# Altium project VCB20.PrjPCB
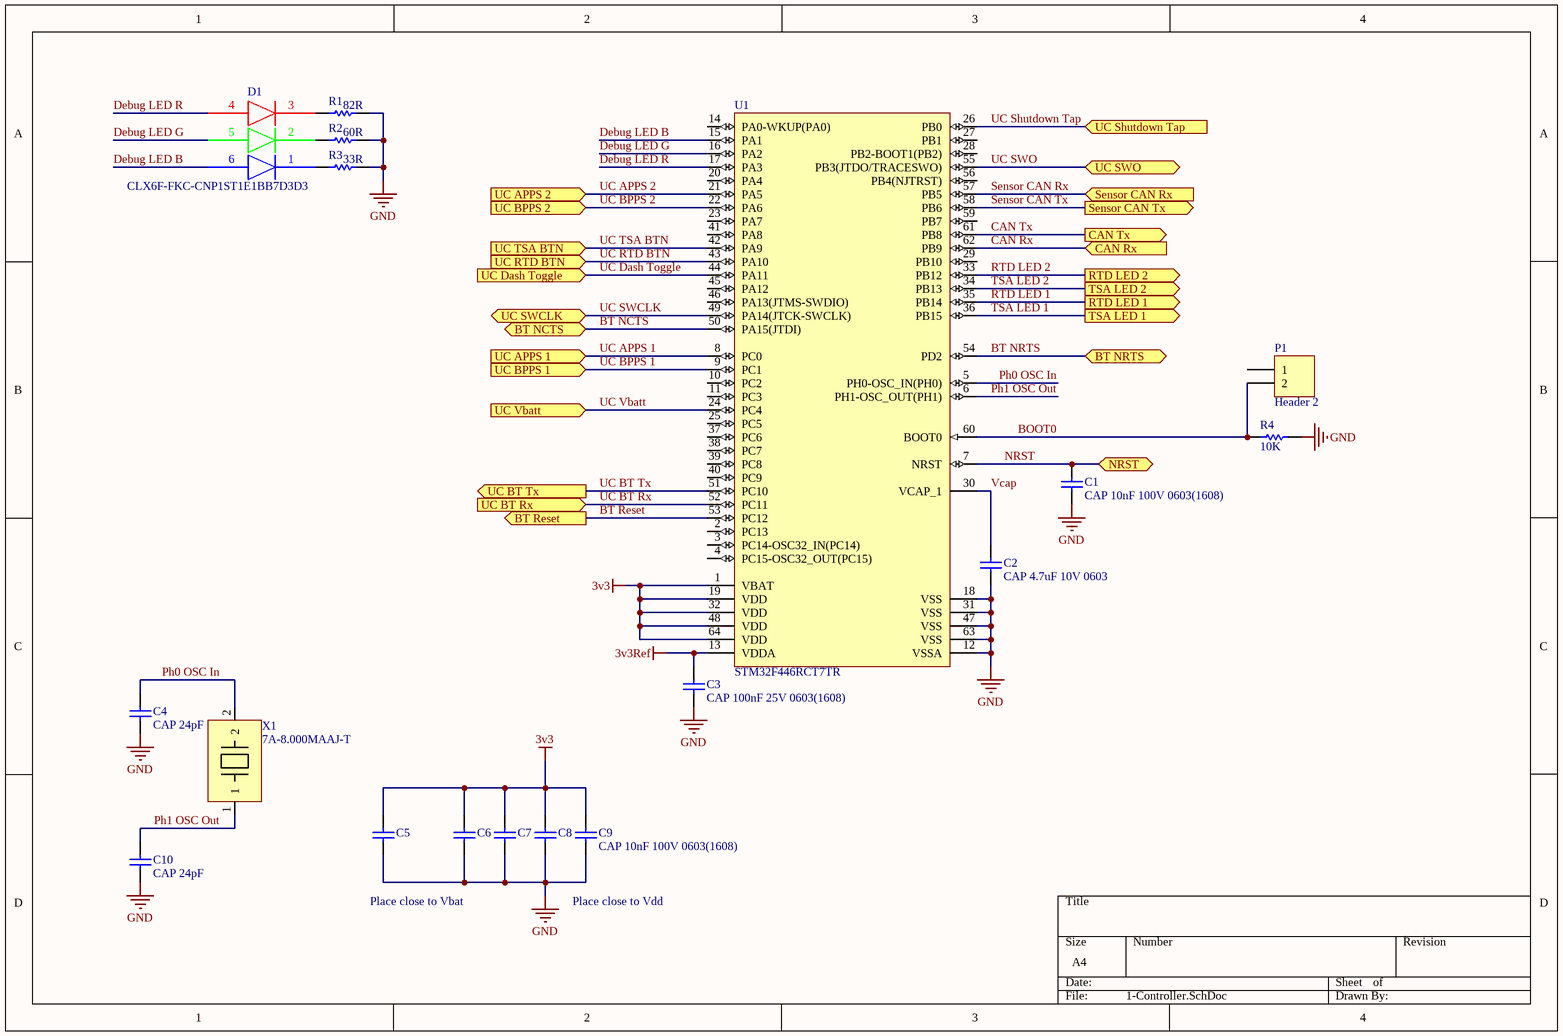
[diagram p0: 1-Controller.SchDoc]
8 sheets, 144 parts. Net scope: flat (ports and power ports of the same name join across sheets).
Board file: VCB2020.PcbDoc
Sheets:
  1-Controller.SchDoc
  2-Power.SchDoc
  3-CAN.SchDoc
  4-PPS.SchDoc
  5-Connector.SchDoc
  8-Bluetooth.SchDoc
  9-Other_Inputs.SchDoc
  10-DashLEDs.SchDoc

## Sheet 1-Controller.SchDoc
size A4

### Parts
C1  CAP 10nF 100V 0603(1608)  [CAPC0603(1608)100_M]
C2  CAP 4.7uF 10V 0603  [CAPC0603(1608)100_M]
C3  CAP 100nF 25V 0603(1608)  [CAPC0603(1608)100_N]
C4  CAP 24pF  [CAPC0603(1608)100_N]
C5  CAP 10nF 100V 0603(1608)  [CAPC0603(1608)100_M]  (value not drawn)
C6  CAP 10nF 100V 0603(1608)  [CAPC0603(1608)100_M]  (value not drawn)
C7  CAP 10nF 100V 0603(1608)  [CAPC0603(1608)100_M]  (value not drawn)
C8  CAP 10nF 100V 0603(1608)  [CAPC0603(1608)100_M]  (value not drawn)
C9  CAP 10nF 100V 0603(1608)  [CAPC0603(1608)100_M]
C10  CAP 24pF  [CAPC0603(1608)100_N]
D1  CLX6F-FKC-CNP1ST1E1BB7D3D3  [CLX6C-FKB]
P1  Header 2  [HDR1X2]
R1  82R  [RESC0603(1608)_N]
R2  60R  [RESC0603(1608)_N]
R3  33R  [RESC0603(1608)_N]
R4  10K  [RESC0603(1608)_N]
U1  STM32F446RCT7TR  [STM-LQFP64_L]
X1  7A-8.000MAAJ-T  [2-SMD, No Lead]

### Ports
BT NCTS (bidir), BT NRTS (bidir), BT Reset (out), CAN Rx (in), CAN Tx (out), NRST (bidir), RTD LED 1 (out), RTD LED 2 (out), Sensor CAN Rx (in), Sensor CAN Tx (out), TSA LED 1 (out), TSA LED 2 (out), UC APPS 1 (in), UC APPS 2 (in), UC BPPS 1 (in), UC BPPS 2 (in), UC BT Rx (in), UC BT Tx (out), UC Dash Toggle (in), UC RTD BTN (in), UC Shutdown Tap (in), UC SWCLK (bidir), UC SWO (bidir), UC TSA BTN (in), UC Vbatt (in)

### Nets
3v3: C5.2 C6.2 C7.2 C8.2 C9.2 U1.1(VBAT) U1.19(VDD) U1.32(VDD) U1.48(VDD) U1.64(VDD)
3v3Ref: C3.2 U1.13(VDDA)
GND: C1.1 C2.1 C3.1 C4.1 C5.1 C6.1 C7.1 C8.1 C9.1 C10.1 R1.2 R2.2 R3.2 R4.2 U1.12(VSSA) U1.18(VSS) U1.31(VSS) U1.47(VSS) U1.63(VSS)
BOOT0: P1.2 R4.1 U1.60(BOOT0)
BT NCTS: U1.50(PA15(JTDI)) ; port BT NCTS
BT NRTS: U1.54(PD2) ; port BT NRTS
BT Reset: U1.53(PC12) ; port BT Reset
CAN Rx: U1.62(PB9) ; port CAN Rx
CAN Tx: U1.61(PB8) ; port CAN Tx
Debug LED B: D1.6(B) U1.15(PA1)
Debug LED G: D1.5(G) U1.16(PA2)
Debug LED R: D1.4(R) U1.17(PA3)
NRST: C1.2 U1.7(NRST) ; port NRST
Ph0 OSC In: C4.2 U1.5(PH0-OSC_IN(PH0)) X1.2
Ph1 OSC Out: C10.2 U1.6(PH1-OSC_OUT(PH1)) X1.1
RTD LED 1: U1.35(PB14) ; port RTD LED 1
RTD LED 2: U1.33(PB12) ; port RTD LED 2
Sensor CAN Rx: U1.57(PB5) ; port Sensor CAN Rx
Sensor CAN Tx: U1.58(PB6) ; port Sensor CAN Tx
TSA LED 1: U1.36(PB15) ; port TSA LED 1
TSA LED 2: U1.34(PB13) ; port TSA LED 2
UC APPS 1: U1.8(PC0) ; port UC APPS 1
UC APPS 2: U1.21(PA5) ; port UC APPS 2
UC BPPS 1: U1.9(PC1) ; port UC BPPS 1
UC BPPS 2: U1.22(PA6) ; port UC BPPS 2
UC BT Rx: U1.52(PC11) ; port UC BT Rx
UC BT Tx: U1.51(PC10) ; port UC BT Tx
UC Dash Toggle: U1.44(PA11) ; port UC Dash Toggle
UC RTD BTN: U1.43(PA10) ; port UC RTD BTN
UC Shutdown Tap: U1.26(PB0) ; port UC Shutdown Tap
UC SWCLK: U1.49(PA14(JTCK-SWCLK)) ; port UC SWCLK
UC SWO: U1.55(PB3(JTDO/TRACESWO)) ; port UC SWO
UC TSA BTN: U1.42(PA9) ; port UC TSA BTN
UC Vbatt: U1.24(PC4) ; port UC Vbatt
Vcap: C2.2 U1.30(VCAP_1)
NetD1_1: D1.1(B) R3.1
NetD1_2: D1.2(G) R2.1
NetD1_3: D1.3(R) R1.1

Not connected (* = marked no-connect by the designer): P1 1; U1 2(PC13) 3(PC14-OSC32_IN(PC14)) 4(PC15-OSC32_OUT(PC15)) 10(PC2) 11(PC3) 14(PA0-WKUP(PA0)) 20(PA4) 23(PA7) 25(PC5) 27(PB1) 28(PB2-BOOT1(PB2)) 29(PB10) 37(PC6) 38(PC7) 39(PC8) 40(PC9) 41(PA8) 45(PA12) 46(PA13(JTMS-SWDIO)) 56(PB4(NJTRST)) 59(PB7)

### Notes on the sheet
- Place close to Vbat
- Place close to Vdd

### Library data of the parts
C1 C5-C9 = CMP-1035-02326-1: CAP 10nF 100V ±20% 0603 (1608 Metric) Thickness 1mm SMD; Case-EIA: 0603; Tolerance: Â±20%; Case-Metric: 1608
C2 = CMP-1035-02787-1: CAP 4.7uF 10V ±20% 0603 (1608 Metric) Thickness 1mm SMD; Case-EIA: 0603; Case-Metric: 1608; Tolerance: Â±20%
C3 = CMP-1035-02589-1: CAP 100nF 25V ±20% 0603 (1608 Metric) Thickness 1mm SMD; Case-EIA: 0603; Tolerance: Â±20%; Case-Metric: 1608
C4 C10 = CMP-1035-00843-1: CAP 24pF 16V ±2% 0603 (1608 Metric) Thickness 1mm SMD; Tolerance: Â±2%; Case-Metric: 1608; Case-EIA: 0603
D1 = LED - CLX6F-FKC-CNP1ST1E1BB7D3D3: Red, Green, Blue (RGB) 622nm Red, 530nm Green, 470nm Blue LED Indication - Discrete 2.1V Red, 2.7V Green, 3V Blue 6-SMD, J-Lead
P1 = Header 2: Header, 2-Pin
R1 = CMP-1012-00048-1: 82R 0.1W 5% 0603 (1608 Metric)  SMD; Case-Metric: 1608; Value: 82.00 Ohm; Case-EIA: 0603
R2 = CMP-1012-00372-1: 60R4 0.1W 1% 0603 (1608 Metric)  SMD; Case-EIA: 0603; Value: 60.40 Ohm; Case-Metric: 1608
R3 = CMP-1012-00038-1: 33R 0.1W 5% 0603 (1608 Metric)  SMD; Value: 33.00 Ohm; Case-EIA: 0603; Case-Metric: 1608
R4 = CMP-1012-00098-1: 10K 0.1W 5% 0603 (1608 Metric)  SMD; Case-EIA: 0603; Value: 10000.00 Ohm; Case-Metric: 1608
U1 = CMP-0243-00217-1: ARM Cortex-M4 32-bit MCU+FPU, 256 KB Flash, 128 KB Internal RAM, 50 I/Os, 64-Pin LQFP, -40 to 105 degC, Tape and Reel; Supply Voltage(Vcc) min (V): 1.7; D/A Converter: 2; Internal RAM Size (kB): 128; FLASH Size (Prog) (kB): 256; I/Os (High Current): 50; Operating Frequency(F) (Processor speed) (MHz): 180
X1 = 8MHz crystal, 7A-8.000MAAJ-T: Manufacturer: TXC CORPORATION; Frequency: 8MHz; Frequency Stability: ±30ppm; Load Capacitance: 18pF; ESR (Equivalent Series Resistance): 80 Ohm; Operating Mode: Fundamental

## Sheet 2-Power.SchDoc
size A4
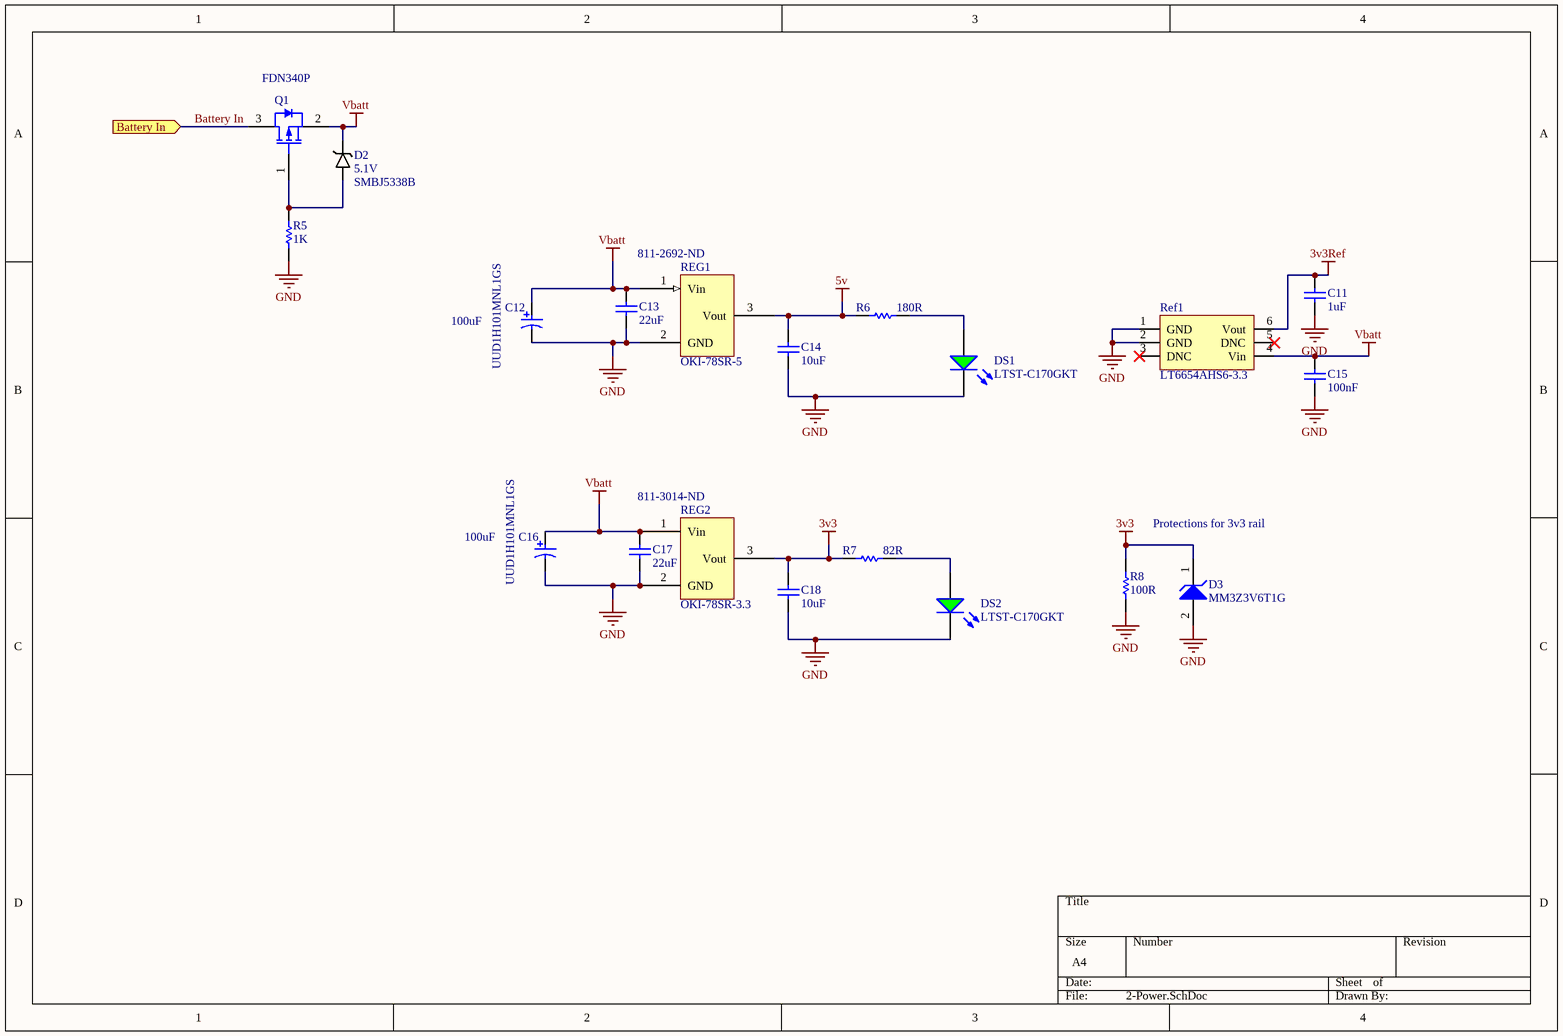
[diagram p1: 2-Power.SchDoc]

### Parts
C11  value 1uF  [1608[0603]]  (hidden comment: Cap)
C12  UUD1H101MNL1GS  [NIC-CAPA2-8X10_V]
C13  value 22uF  [C1210_M]  (hidden comment: Cap)
C14  value 10uF  [C1210_M]  (hidden comment: Cap)
C15  value 100nF  [1608[0603]]  (hidden comment: Cap)
C16  UUD1H101MNL1GS  [NIC-CAPA2-8X10_V]
C17  value 22uF  [C1210_M]  (hidden comment: Cap)
C18  value 10uF  [C1210_M]  (hidden comment: Cap)
D2  Reverse Voltage: 5.1V  Part Number: SMBJ5338B  [DO-214AA (SMB)]  (hidden comment: Zener Diode, 5.1V, 5W SMBJ5338B)
D3  MM3Z3V6T1G  [ONSC-SOD-323-2-477-02_V]
DS1  LTST-C170GKT  [LTST-C170GKT_V]
DS2  LTST-C170GKT  [LTST-C170GKT_V]
Q1  FDN340P  [FAIR-SSOT3L-3_V]
R5  value 1K  [1608[0603]]  (hidden comment: Res1)
R6  value 180R  [1608[0603]]  (hidden comment: Res1)
R7  value 82R  [1608[0603]]  (hidden comment: Res1)
R8  100R  [RESC1206(3216)_M]
Ref1  LT6654AHS6-3.3  [TSOT-23 S6]
REG1  OKI-78SR-5  Supplier Part Number 2: 811-2692-ND  [Reg - TH, 3 pin, 100 mil Pitch, HTL]
REG2  OKI-78SR-3.3  Supplier Part Number 2: 811-3014-ND  [Reg - TH, 3 pin, 100 mil Pitch, VTL]

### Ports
Battery In (in)

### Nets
3v3: C18.2 D3.1(K) R7.1 R8.2 REG2.3(Vout)
3v3Ref: C11.2 Ref1.6(Vout)
5v: C14.2 R6.1 REG1.3(Vout)
GND: C11.1 C12.2 C13.1 C14.1 C15.1 C16.2 C17.1 C18.1 D3.2(A) DS1.2(K) DS2.2(K) R5.1 R8.1 Ref1.1(GND) Ref1.2(GND) REG1.2(GND) REG2.2(GND)
Vbatt: C12.1 C13.2 C15.2 C16.1 C17.2 D2.K Q1.2(SOURCE) Ref1.4(Vin) REG1.1(Vin) REG2.1(Vin)
Battery In: Q1.3(DRAIN) ; port Battery In
NetD2_A: D2.A Q1.1(GATE) R5.2
NetDS1_1: DS1.1(A) R6.2
NetDS2_1: DS2.1(A) R7.2

Not connected (* = marked no-connect by the designer): Ref1 3(DNC)* 5(DNC)*

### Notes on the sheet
- (near C12) 100uF
- (near C16) 100uF
- Protections for 3v3 rail

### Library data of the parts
C11 = Cap: Capacitor; Manufacturer: Murata Electronics North America; Manufacturer Part Number: GRM188R61E105KA12D; Capacitance: 1µF; Tolerance: ±10%; Voltage - Rated: 25V; Temperature Coefficient: X5R
C12 C16 = CMP-0687-00073-1: Aluminum Electrolytic Capacitor, UD Series, Low Impedance, 100 uF, 50 V, + / - 20%, -55 to 105 degC, Chip Type, 8 x 10 mm D x L, Pb-Free, Reel; Manufacturer: Nichicon; Rated Ripple Current (at 100kHz): 300 mA; Tolerance Rated Capacitance: -20 to 20%; Packing: Dia382mm Reel; Impedance: 0.34 Ohm; Rated Voltage: 50 V; Endurance Time: 5000 h; Rated Capacitance: 100 uF; Capacitance: 100µF; Voltage Rating: 50V; Lifetime @ Temp.: 5000 Hrs @ 105°C; Polarization: Polar; Ripple Current: 300mA; Surface Mount Land Size: 0.327" L x 0.327" W (8.30mm x 8.30mm)
C13 C17 = Cap: Capacitor; Manufacturer: Yageo; Manufacturer Part Number: CC1210MKX5R8BB226; Capacitance: 22µF; Tolerance: ±20%; Voltage - Rated: 25V; Temperature Coefficient: X5R
C14 C18 = Cap: Capacitor; Manufacturer: Yageo; Manufacturer Part Number: CC1210ZKY5V8BB106; Capacitance: 10µF; Tolerance: -20%, +80%; Voltage - Rated: 25V; Temperature Coefficient: Y5V (F)
C15 = Cap: Capacitor; Manufacturer: Yageo; Manufacturer Part Number: CC0603KRX7R9BB104; Capacitance: 0.10µF; Tolerance: ±10%; Voltage - Rated: 50V; Temperature Coefficient: X7R
D3 = CMP-1060-00650-1: Zener Voltage Regulator, 300 mW, 2-Pin SOD-323, Pb-Free, Tape and Reel; Manufacturer: On Semiconductor; VZ Typ (V): 3.6; P Max (W): 0.3
DS1 DS2 = CMP-1674-00002-5: LED Uni-Color Green, 100 mW, 120 mA, -55 to 85 degC, 2-Pin SMD, RoHS, Tape and Reel; Manufacturer: Lite-On; Lens Color: Colorless; Lens Transparency: Clear; Millicandela Rating: 6mcd; Lens Style/Size: Rectangle with Flat Top, 1.40mm x 1.25mm; Voltage - Forward (Vf) (Typ): 2.1V; Current - Test: 10mA; Viewing Angle: 130°; Wavelength - Dominant: 569nm; Wavelength - Peak: 565nm
Q1 = CMP-2100-03638-1: Single P-Channel, Logic Level, PowerTrench(R) MOSFET, 2 A, 20 V, -55 to 150 degC, 3-Pin SOT-23, RoHS, Tape and Reel; Manufacturer: Fairchild Semiconductor; Fall Time: 11ns; Current Rating: -2A; Turn-On Delay Time: 10ns; Drain to Source Breakdown Voltage: -20V; Drain to Source Resistance: 60mOhm; Gate to Source Voltage (Vgs): 8V; Threshold Voltage: -800mV; Rds On Max: 70mOhm; Package Version: Rev. 3, 05/2015; Turn-Off Delay Time: 27ns; Power Dissipation: 500mW; Number of Elements: 1; Drain to Source Voltage (Vdss): 20V; Rise Time: 9ns; Input Capacitance: 779pF; Continuous Drain Current (ID): 2A
R5 = Res1: Resistor; Manufacturer: Panasonic Electronic Components; Manufacturer Part Number: ERJ-PA3F1001V; Tolerance: ±1%; Power (Watts): 0.25W, 1/4W; Temperature Coefficient: ±100ppm/°C
R6 = Res1: Resistor; Manufacturer: Yageo; Manufacturer Part Number: RC0603JR-07180RL; Resistance (Ohms): 180; Tolerance: ±5%; Power (Watts): 0.1W, 1/10W; Temperature Coefficient: ±100ppm/°C
R7 = Res1: Resistor; Manufacturer: Yageo; Manufacturer Part Number: RC0603JR-0782RL; Resistance (Ohms): 82; Tolerance: ±5%; Power (Watts): 0.1W, 1/10W; Temperature Coefficient: ±100ppm/°C
R8 = CMP-1014-00050-1: 100R 0.25W 5% 1206 (3216 Metric)  SMD; Case-EIA: 1206; Value: 100.00 Ohm; Case-Metric: 3216
Ref1 = LT6654AHS6-3.3: Manufacturer: Linear Technology; Reference Type: Series; Output Type: Fixed; Voltage - Output (Min/Fixed): 3.3V; Current - Output: 10mA; Tolerance: ±0.05%; Temperature Coefficient: 10ppm/°C; Noise - 0.1Hz to 10Hz: 1.7ppmp-p; Noise - 10Hz to 10kHz: 2ppmrms; Voltage - Input: 3.8 V ~ 36 V; Current - Supply: 600µA
REG1 = OKI-78SR-5: Manufacturer: Murata Power Solutions Inc.; Manufacturer Part Number: OKI-78SR-3.3/1.5-W36-C; Power (Watts) - Manufacture Series: 5W; Number of Outputs: 1; Voltage - Input (Min): 7V; Voltage - Input (Max): 36V; Voltage - Output 1: 3.3V; Current - Output (Max): 1.5A; Efficiency: 85.5%
REG2 = OKI-78SR-5: 3.3V DCDC; Manufacturer: Murata Power Solutions Inc.; Manufacturer Part Number: OKI-78SR-3.3/1.5-W36H-C; Power (Watts) - Manufacture Series: 5W; Number of Outputs: 1; Voltage - Input (Min): 7V; Voltage - Input (Max): 36V; Current - Output (Max): 1.5A; Efficiency: 85.5%

## Sheet 3-CAN.SchDoc
size A4
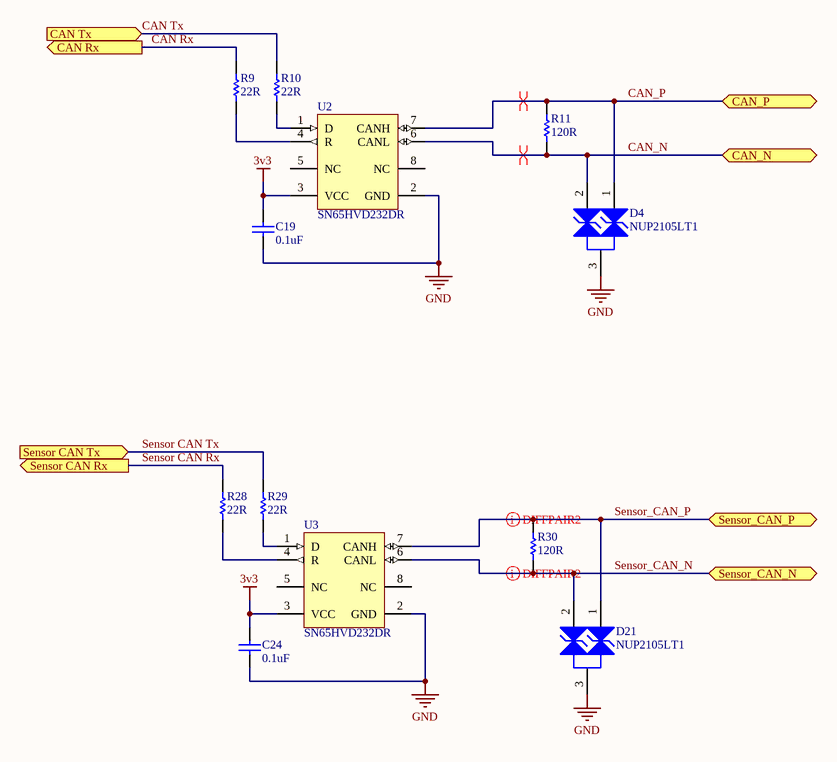
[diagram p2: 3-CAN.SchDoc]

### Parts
C19  0.1uF  [CAPC1608X90X30NL10T20]
C24  0.1uF  [CAPC1608X90X30NL10T20]
D4  NUP2105LT1  [ONSC-SOT-23-3-318-08_V]
D21  NUP2105LT1  [ONSC-SOT-23-3-318-08_V]
R9  22R  [RESC0603(1608)_N]
R10  22R  [RESC0603(1608)_N]
R11  120R  [RESC0603(1608)_N]
R28  22R  [RESC0603(1608)_N]
R29  22R  [RESC0603(1608)_N]
R30  120R  [RESC0603(1608)_N]
U2  SN65HVD232DR  [D0008A_M]
U3  SN65HVD232DR  [D0008A_M]

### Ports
CAN Rx (out), CAN Tx (in), CAN_N (bidir), CAN_P (bidir), Sensor CAN Rx (out), Sensor CAN Tx (in), Sensor_CAN_N (bidir), Sensor_CAN_P (bidir)

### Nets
3v3: C19.2 C24.2 U2.3(VCC) U3.3(VCC)
GND: C19.1 C24.1 D4.3(K) D21.3(K) U2.2(GND) U3.2(GND)
CAN Rx: R9.2 ; port CAN Rx
CAN Tx: R10.2 ; port CAN Tx
CAN_N: D4.2(K) R11.1 U2.6(CANL) ; port CAN_N
CAN_P: D4.1(K) R11.2 U2.7(CANH) ; port CAN_P
Sensor CAN Rx: R28.2 ; port Sensor CAN Rx
Sensor CAN Tx: R29.2 ; port Sensor CAN Tx
Sensor_CAN_N: D21.2(K) R30.1 U3.6(CANL) ; port Sensor_CAN_N
Sensor_CAN_P: D21.1(K) R30.2 U3.7(CANH) ; port Sensor_CAN_P
NetR9_1: R9.1 U2.4(R)
NetR10_1: R10.1 U2.1(D)
NetR28_1: R28.1 U3.4(R)
NetR29_1: R29.1 U3.1(D)

Not connected (* = marked no-connect by the designer): U2 5(NC) 8(NC); U3 5(NC) 8(NC)

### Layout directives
differential pair: CAN_N, CAN_P, Sensor_CAN_N, Sensor_CAN_P

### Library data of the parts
C19 C24 = CMP-2000-06092-1: Chip Capacitor, 100 nF, +/- 10%, 50 V, -55 to 125 degC, 0603 (1608 Metric), RoHS, Tape and Reel; Manufacturer: SamsungElectro-Mechanics; Product Length: 1.6mm; Voltage: 50Vdc; Product Height: 0.8mm; Rad Hard: No; Dielectric: X7R
D4 D21 = CMP-1063-00165-1: Dual Line CAN Bus Protector, 3-Pin SOT-23, Tape and Reel; Manufacturer: On Semiconductor; PPK Max (W): 350; IR Max (uA): 0.1; Number of Lines: 2; V(BR) Min (V): 26.2; Direction: Bidirectional; C Max (pF): 30
R9 R10 R28 R29 = CMP-1012-00034-1: 22R 0.1W 5% 0603 (1608 Metric)  SMD; Value: 22.00 Ohm; Case-EIA: 0603; Case-Metric: 1608
R11 R30 = CMP-1012-00052-1: 120R 0.1W 5% 0603 (1608 Metric)  SMD; Case-EIA: 0603; Value: 120.00 Ohm; Case-Metric: 1608
U2 U3 = CMP-0315-00075-2: 3.3 V Can Transceiver, 17 mA, -40 to 85 degC, 8-pin SOIC (D), Green (RoHS & no Sb/Br); Manufacturer: Texas Instruments; Supply Voltage(s)(V): 3.3; Receivers Per Package: 1; ICC(Max)(mA): 17; Rating: Catalog; Transient Pulse Protection(V): -25 to 25

## Sheet 4-PPS.SchDoc
size A4
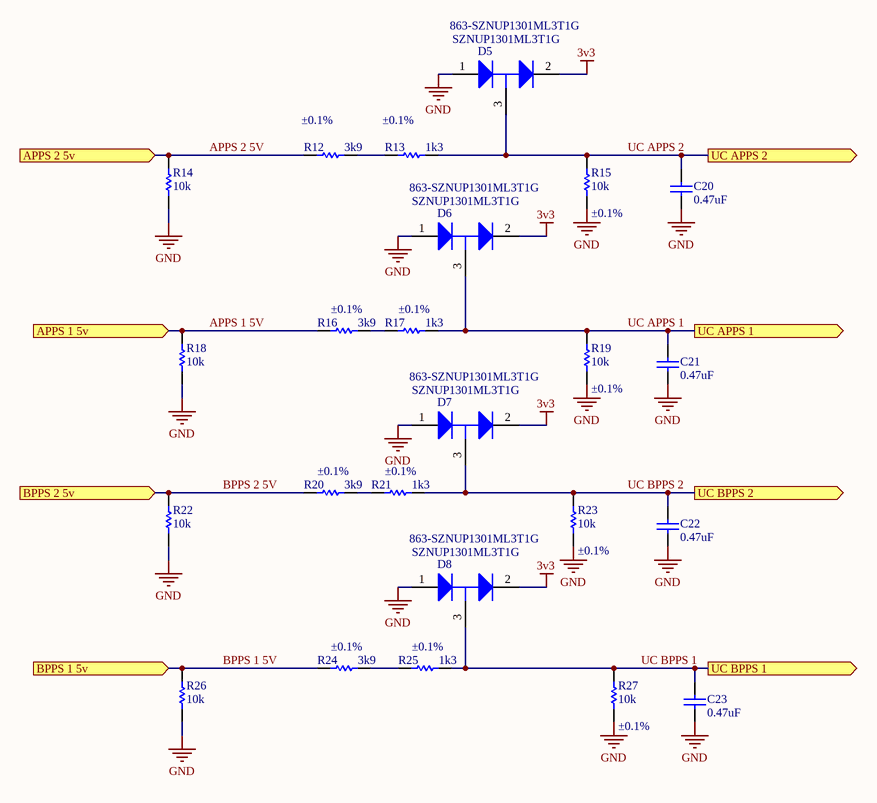
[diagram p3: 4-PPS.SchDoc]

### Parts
C20  value 0.47uF  [1608[0603]]  (hidden comment: Cap)
C21  value 0.47uF  [1608[0603]]  (hidden comment: Cap)
C22  value 0.47uF  [1608[0603]]  (hidden comment: Cap)
C23  value 0.47uF  [1608[0603]]  (hidden comment: Cap)
D5  SZNUP1301ML3T1G  Supplier Part Number 1: 863-SZNUP1301ML3T1G  [ONSC-SOT-23-3-318-08_V]
D6  SZNUP1301ML3T1G  Supplier Part Number 1: 863-SZNUP1301ML3T1G  [ONSC-SOT-23-3-318-08_V]
D7  SZNUP1301ML3T1G  Supplier Part Number 1: 863-SZNUP1301ML3T1G  [ONSC-SOT-23-3-318-08_V]
D8  SZNUP1301ML3T1G  Supplier Part Number 1: 863-SZNUP1301ML3T1G  [ONSC-SOT-23-3-318-08_V]
R12  value 3k9  Tolerance: ±0.1%  [1608[0603]]  (hidden comment: Res1)
R13  value 1k3  Tolerance: ±0.1%  [1608[0603]]  (hidden comment: Res1)
R14  value 10k  [1608[0603]]  (hidden comment: Res1)
R15  value 10k  Tolerance: ±0.1%  [1608[0603]]  (hidden comment: Res1)
R16  value 3k9  Tolerance: ±0.1%  [1608[0603]]  (hidden comment: Res1)
R17  value 1k3  Tolerance: ±0.1%  [1608[0603]]  (hidden comment: Res1)
R18  value 10k  [1608[0603]]  (hidden comment: Res1)
R19  value 10k  Tolerance: ±0.1%  [1608[0603]]  (hidden comment: Res1)
R20  value 3k9  Tolerance: ±0.1%  [1608[0603]]  (hidden comment: Res1)
R21  value 1k3  Tolerance: ±0.1%  [1608[0603]]  (hidden comment: Res1)
R22  value 10k  [1608[0603]]  (hidden comment: Res1)
R23  value 10k  Tolerance: ±0.1%  [1608[0603]]  (hidden comment: Res1)
R24  value 3k9  Tolerance: ±0.1%  [1608[0603]]  (hidden comment: Res1)
R25  value 1k3  Tolerance: ±0.1%  [1608[0603]]  (hidden comment: Res1)
R26  value 10k  [1608[0603]]  (hidden comment: Res1)
R27  value 10k  Tolerance: ±0.1%  [1608[0603]]  (hidden comment: Res1)

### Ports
APPS 1 5v (in), APPS 2 5v (in), BPPS 1 5v (in), BPPS 2 5v (in), UC APPS 1 (out), UC APPS 2 (out), UC BPPS 1 (out), UC BPPS 2 (out)

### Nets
3v3: D5.2(K) D6.2(K) D7.2(K) D8.2(K)
GND: C20.1 C21.1 C22.1 C23.1 D5.1(A) D6.1(A) D7.1(A) D8.1(A) R14.1 R15.1 R18.1 R19.1 R22.1 R23.1 R26.1 R27.1
APPS 1 5V: R16.1 R18.2 ; port APPS 1 5v
APPS 2 5V: R12.1 R14.2 ; port APPS 2 5v
BPPS 1 5V: R24.1 R26.2 ; port BPPS 1 5v
BPPS 2 5V: R20.1 R22.2 ; port BPPS 2 5v
UC APPS 1: C21.2 D6.3(K/A) R17.2 R19.2 ; port UC APPS 1
UC APPS 2: C20.2 D5.3(K/A) R13.2 R15.2 ; port UC APPS 2
UC BPPS 1: C23.2 D8.3(K/A) R25.2 R27.2 ; port UC BPPS 1
UC BPPS 2: C22.2 D7.3(K/A) R21.2 R23.2 ; port UC BPPS 2
NetR12_2: R12.2 R13.1
NetR16_2: R16.2 R17.1
NetR20_2: R20.2 R21.1
NetR24_2: R24.2 R25.1

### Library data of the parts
C20-C23 = Cap: Capacitor; Manufacturer: Yageo; Manufacturer Part Number: CC0603KRX7R8BB474; Capacitance: 0.47µF; Tolerance: ±10%; Voltage - Rated: 25V; Temperature Coefficient: X7R
D5-D8 = CMP-1063-00171-1: Low Capacitance Diode Array for ESD Protection in a Single Data Line, 3-Pin SOT-23, Pb-Free, Tape and Reel; Manufacturer: On Semiconductor; C Max (pF): 0.9; Direction: Bidirectional; V(BR) Min (V): 70; Number of Lines: 1
R12 R16 R20 R24 = Res1: Resistor; Manufacturer: Yageo; Manufacturer Part Number: RT0603BRD073K9L; Resistance (Ohms): 3.9k; Power (Watts): 0.1W, 1/10W; Temperature Coefficient: ±25ppm/°C
R13 R17 R21 R25 = Res1: Resistor; Manufacturer: Yageo; Manufacturer Part Number: RT0603BRD071K3L; Resistance (Ohms): 1.3k; Power (Watts): 0.1W, 1/10W; Temperature Coefficient: ±25ppm/°C
R14 R18 R22 R26 = Res1: Resistor; Manufacturer: Yageo; Manufacturer Part Number: RC0603JR-0710KL; Tolerance: ±5%; Power (Watts): 0.1W, 1/10W; Temperature Coefficient: ±100ppm/°C
R15 R19 R23 R27 = Res1: Resistor; Manufacturer: Yageo; Manufacturer Part Number: RT0603BRD0710KL; Power (Watts): 0.1W, 1/10W; Temperature Coefficient: ±25ppm/°C

## Sheet 5-Connector.SchDoc
size A4
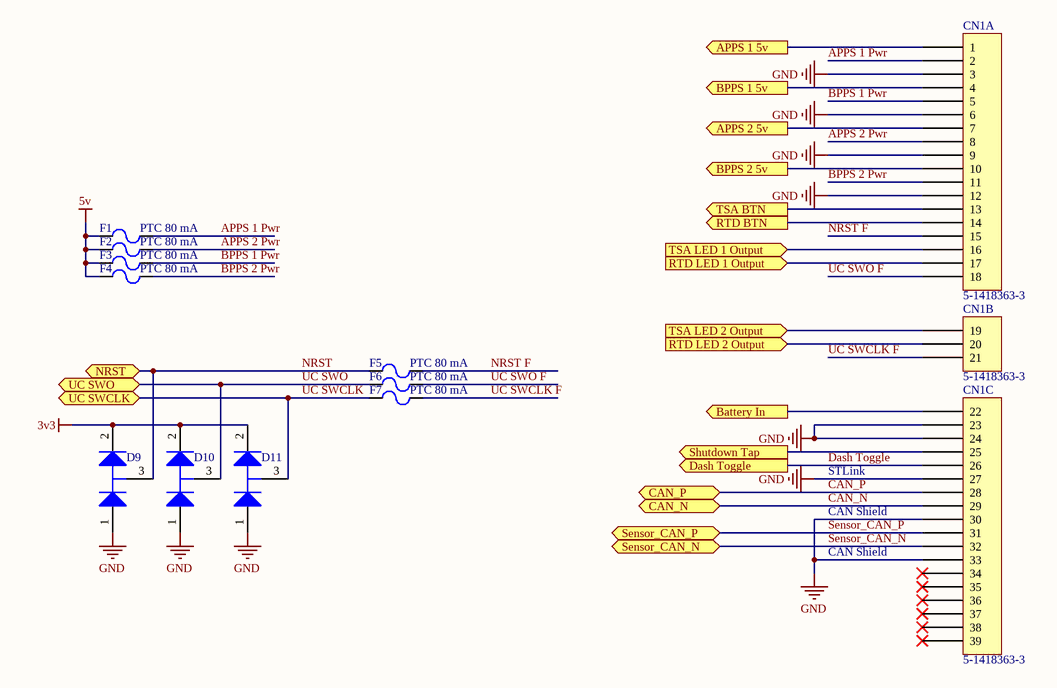
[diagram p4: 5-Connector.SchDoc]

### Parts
CN1  5-1418363-3  [5-1418363-3]  (parts A,B,C of 3)
D9  SZNUP1301ML3T1G  [ONSC-SOT-23-3-318-08_V]  (value not drawn)
D10  SZNUP1301ML3T1G  [ONSC-SOT-23-3-318-08_V]  (value not drawn)
D11  SZNUP1301ML3T1G  [ONSC-SOT-23-3-318-08_V]  (value not drawn)
F1  PTC 80 mA  [0603 fuse]
F2  PTC 80 mA  [0603 fuse]
F3  PTC 80 mA  [0603 fuse]
F4  PTC 80 mA  [0603 fuse]
F5  PTC 80 mA  [0603 fuse]
F6  PTC 80 mA  [0603 fuse]
F7  PTC 80 mA  [0603 fuse]

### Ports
APPS 1 5v (out), APPS 2 5v (out), Battery In (out), BPPS 1 5v (out), BPPS 2 5v (out), CAN_N (bidir), CAN_P (bidir), Dash Toggle (out), NRST (bidir), RTD BTN (out), RTD LED 1 Output (in), RTD LED 2 Output (in), Sensor_CAN_N (bidir), Sensor_CAN_P (bidir), Shutdown Tap (out), TSA BTN (out), TSA LED 1 Output (in), TSA LED 2 Output (in), UC SWCLK (bidir), UC SWO (bidir)

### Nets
3v3: D9.2(K) D10.2(K) D11.2(K)
5v: F1.1 F2.1 F3.1 F4.1
GND: CN1.3 CN1.6 CN1.9 CN1.12 CN1.23 CN1.24 CN1.27 CN1.30 CN1.33 D9.1(A) D10.1(A) D11.1(A)
APPS 1 5V: CN1.1 ; port APPS 1 5v
APPS 1 Pwr: CN1.2 F1.2
APPS 2 5V: CN1.7 ; port APPS 2 5v
APPS 2 Pwr: CN1.8 F2.2
Battery In: CN1.22 ; port Battery In
BPPS 1 5V: CN1.4 ; port BPPS 1 5v
BPPS 1 Pwr: CN1.5 F3.2
BPPS 2 5V: CN1.10 ; port BPPS 2 5v
BPPS 2 Pwr: CN1.11 F4.2
CAN_N: CN1.29 ; port CAN_N
CAN_P: CN1.28 ; port CAN_P
Dash Toggle: CN1.26 ; port Dash Toggle
NRST: D9.3(K/A) F5.1 ; port NRST
NRST F: CN1.15 F5.2
RTD BTN: CN1.14 ; port RTD BTN
RTD LED Output 1: CN1.17 ; port RTD LED 1 Output
RTD LED Output 2: CN1.20 ; port RTD LED 2 Output
Sensor_CAN_N: CN1.32 ; port Sensor_CAN_N
Sensor_CAN_P: CN1.31 ; port Sensor_CAN_P
Shutdown_Tap: CN1.25 ; port Shutdown Tap
TSA BTN: CN1.13 ; port TSA BTN
TSA LED Output 1: CN1.16 ; port TSA LED 1 Output
TSA LED Output 2: CN1.19 ; port TSA LED 2 Output
UC SWCLK: D11.3(K/A) F7.1 ; port UC SWCLK
UC SWCLK F: CN1.21 F7.2
UC SWO: D10.3(K/A) F6.1 ; port UC SWO
UC SWO F: CN1.18 F6.2

Not connected (* = marked no-connect by the designer): CN1 34* 35* 36* 37* 38* 39*

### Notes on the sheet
- STLink
- CAN Shield

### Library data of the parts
CN1 = 5-1418363-3: Levyseal 90 degree 39 pin header
D9-D11 = CMP-1063-00171-1: as D5 on sheet 4-PPS
F1-F7 = PTC fuse 80mA 0ZCM0008FF2G: 0ZCM0008FF2G

## Sheet 8-Bluetooth.SchDoc
size A4
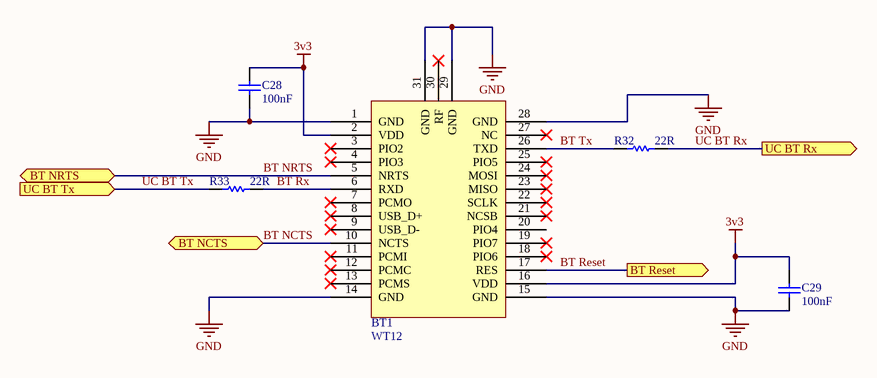
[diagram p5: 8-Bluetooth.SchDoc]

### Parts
BT1  WT12  [WT12]
C28  value 100nF  [1608[0603]]  (hidden comment: Cap)
C29  value 100nF  [1608[0603]]  (hidden comment: Cap)
R32  value 22R  [1608[0603]]  (hidden comment: Res1)
R33  value 22R  [1608[0603]]  (hidden comment: Res1)

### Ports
BT NCTS (bidir), BT NRTS (bidir), BT Reset (out), UC BT Rx (out), UC BT Tx (in)

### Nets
3v3: BT1.2(VDD) BT1.16(VDD) C28.2 C29.2
GND: BT1.1(GND) BT1.14(GND) BT1.15(GND) BT1.28(GND) BT1.29(GND) BT1.31(GND) C28.1 C29.1
BT NCTS: BT1.10(NCTS) ; port BT NCTS
BT NRTS: BT1.5(NRTS) ; port BT NRTS
BT Reset: BT1.17(RES) ; port BT Reset
BT Rx: BT1.6(RXD) R33.2
BT Tx: BT1.26(TXD) R32.1
UC BT Rx: R32.2 ; port UC BT Rx
UC BT Tx: R33.1 ; port UC BT Tx

Not connected (* = marked no-connect by the designer): BT1 3(PIO2)* 4(PIO3)* 7(PCMO)* 8(USB_D+)* 9(USB_D-)* 11(PCMI)* 12(PCMC)* 13(PCMS)* 18(PIO6)* 19(PIO7)* 20(PIO4) 21(NCSB)* 22(SCLK)* 23(MISO)* 24(MOSI)* 25(PIO5)* 27(NC)* 30(RF)*

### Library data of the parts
C28 C29 = Cap: as C15 on sheet 2-Power
R32 R33 = Res1: Resistor; Manufacturer: Yageo; Manufacturer Part Number: RC0603JR-0722RL; Resistance (Ohms): 22; Tolerance: ±5%; Power (Watts): 0.1W, 1/10W; Temperature Coefficient: ±100ppm/°C

## Sheet 9-Other_Inputs.SchDoc
size A4
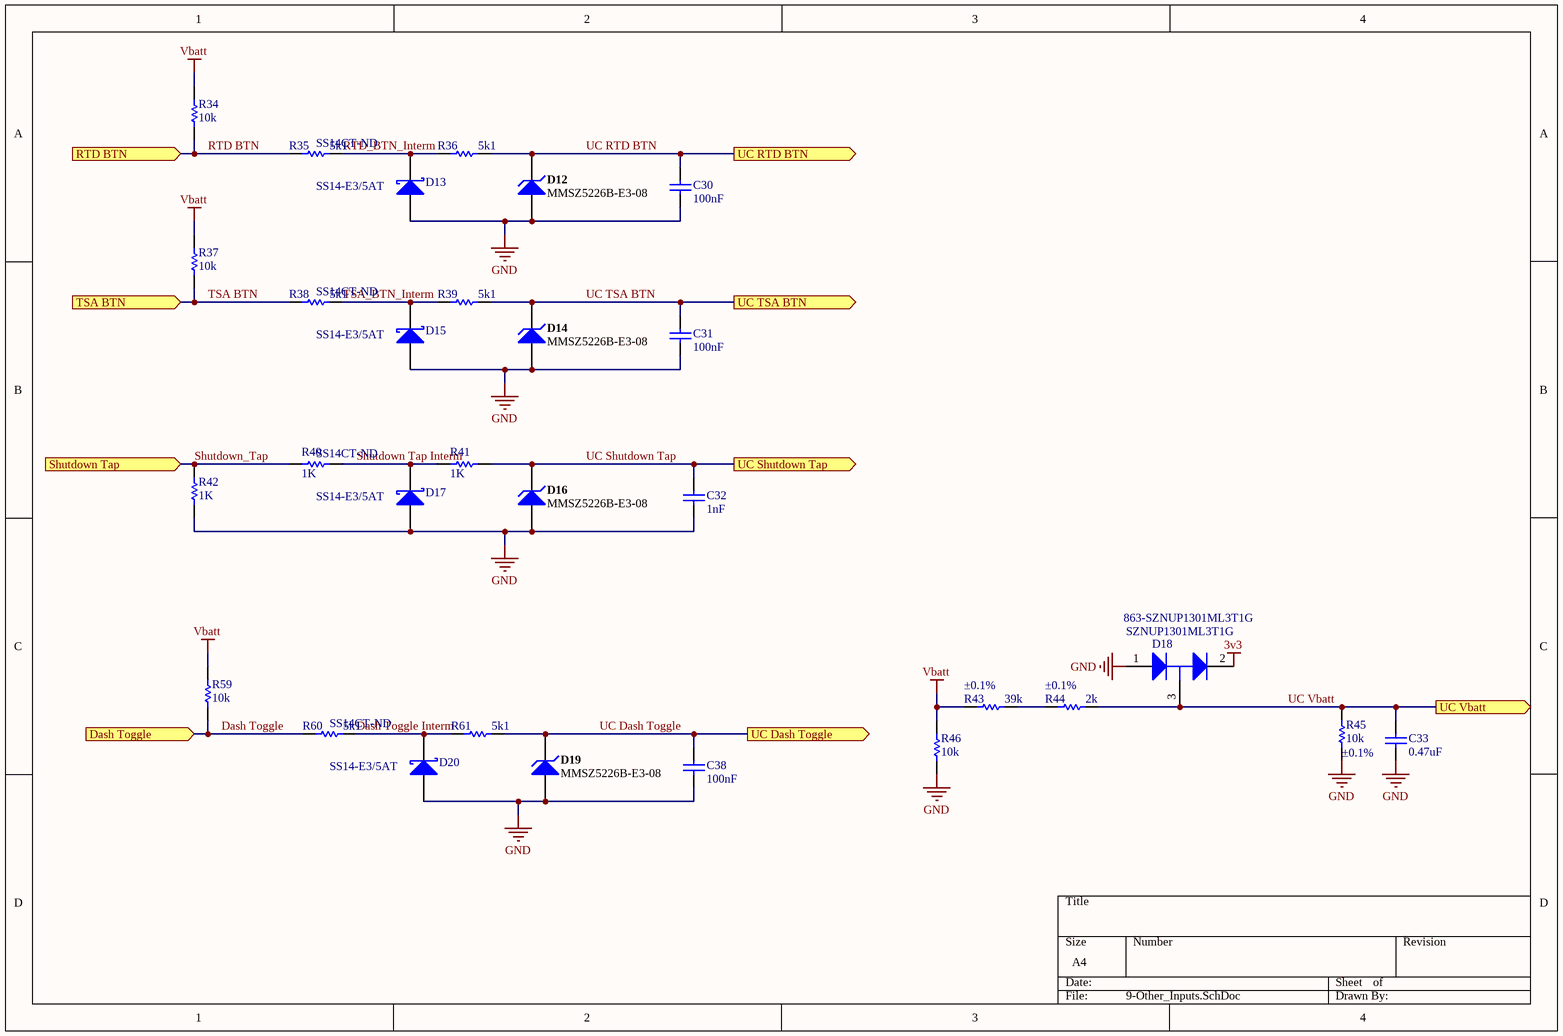
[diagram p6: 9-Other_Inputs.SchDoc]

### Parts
C30  value 100nF  [1608[0603]]  (hidden comment: Cap)
C31  value 100nF  [1608[0603]]  (hidden comment: Cap)
C32  value 1nF  [1608[0603]]  (hidden comment: Cap)
C33  value 0.47uF  [1608[0603]]  (hidden comment: Cap)
C38  value 100nF  [1608[0603]]  (hidden comment: Cap)
D12  MMSZ5226B-E3-08  [VISH-SOD-123-2_V]
D13  SS14-E3/5AT  Supplier Part Number 1: SS14CT-ND  [VISH-DO-214AC-2_V]
D14  MMSZ5226B-E3-08  [VISH-SOD-123-2_V]
D15  SS14-E3/5AT  Supplier Part Number 1: SS14CT-ND  [VISH-DO-214AC-2_V]
D16  MMSZ5226B-E3-08  [VISH-SOD-123-2_V]
D17  SS14-E3/5AT  Supplier Part Number 1: SS14CT-ND  [VISH-DO-214AC-2_V]
D18  SZNUP1301ML3T1G  Supplier Part Number 1: 863-SZNUP1301ML3T1G  [ONSC-SOT-23-3-318-08_V]
D19  MMSZ5226B-E3-08  [VISH-SOD-123-2_V]
D20  SS14-E3/5AT  Supplier Part Number 1: SS14CT-ND  [VISH-DO-214AC-2_V]
R34  value 10k  [1608[0603]]  (hidden comment: Res1)
R35  value 5k1  [1608[0603]]  (hidden comment: Res1)
R36  value 5k1  [1608[0603]]  (hidden comment: Res1)
R37  value 10k  [1608[0603]]  (hidden comment: Res1)
R38  value 5k1  [1608[0603]]  (hidden comment: Res1)
R39  value 5k1  [1608[0603]]  (hidden comment: Res1)
R40  value 1K  [1608[0603]]  (hidden comment: Res1)
R41  value 1K  [1608[0603]]  (hidden comment: Res1)
R42  value 1K  [1608[0603]]  (hidden comment: Res1)
R43  value 39k  Tolerance: ±0.1%  [1608[0603]]  (hidden comment: Res1)
R44  value 2k  Tolerance: ±0.1%  [1608[0603]]  (hidden comment: Res1)
R45  value 10k  Tolerance: ±0.1%  [1608[0603]]  (hidden comment: Res1)
R46  value 10k  [1608[0603]]  (hidden comment: Res1)
R59  value 10k  [1608[0603]]  (hidden comment: Res1)
R60  value 5k1  [1608[0603]]  (hidden comment: Res1)
R61  value 5k1  [1608[0603]]  (hidden comment: Res1)

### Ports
Dash Toggle (in), RTD BTN (in), Shutdown Tap (in), TSA BTN (in), UC Dash Toggle (out), UC RTD BTN (out), UC Shutdown Tap (out), UC TSA BTN (out), UC Vbatt (out)

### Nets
3v3: D18.2(K)
GND: C30.1 C31.1 C32.1 C33.1 C38.1 D12.1(A) D13.1(A) D14.1(A) D15.1(A) D16.1(A) D17.1(A) D18.1(A) D19.1(A) D20.1(A) R42.1 R45.1 R46.1
Vbatt: R34.2 R37.2 R43.1 R46.2 R59.2
Dash Toggle: R59.1 R60.1 ; port Dash Toggle
Dash Toggle Interm: D20.2(K) R60.2 R61.1
RTD BTN: R34.1 R35.1 ; port RTD BTN
RTD_BTN_Interm: D13.2(K) R35.2 R36.1
Shutdown Tap Interm: D17.2(K) R40.1 R41.2
Shutdown_Tap: R40.2 R42.2 ; port Shutdown Tap
TSA BTN: R37.1 R38.1 ; port TSA BTN
TSA_BTN_Interm: D15.2(K) R38.2 R39.1
UC Dash Toggle: C38.2 D19.2(K) R61.2 ; port UC Dash Toggle
UC RTD BTN: C30.2 D12.2(K) R36.2 ; port UC RTD BTN
UC Shutdown Tap: C32.2 D16.2(K) R41.1 ; port UC Shutdown Tap
UC TSA BTN: C31.2 D14.2(K) R39.2 ; port UC TSA BTN
UC Vbatt: C33.2 D18.3(K/A) R44.2 R45.2 ; port UC Vbatt
NetR43_2: R43.2 R44.1

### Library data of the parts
C30 C31 C38 = Cap: as C15 on sheet 2-Power
C32 = Cap: Capacitor; Manufacturer: Yageo; Manufacturer Part Number: CC0603KRX7R9BB102; Capacitance: 1000pF; Tolerance: ±10%; Voltage - Rated: 50V; Temperature Coefficient: X7R
C33 = Cap: as C20 on sheet 4-PPS
D12 D14 D16 D19 = CMP-0931-00026-1: Small Signal Zener Diode, 3.3 V +/- 5%, -55 to 155 degC, 2-Pin SOD-123, RoHS, Tape and Reel; Manufacturer: Vishay Semiconductor; Manufacturer Part Number: MMSZ5226B-7-F; Tolerance: +/- 5%; Test Current (IZT1) (mA): 20; Power Dissipation (mW): 500; Int. Construction: Single; Zener Impedance (IZT1) (Max.) (Ohm): 28; Zener Voltage (NOM.) (V): 3.3; Voltage - Zener (Nom) (Vz): 3.3V; Power - Max: 500mW; Impedance (Max) (Zzt): 28 Ohm; Current - Reverse Leakage @ Vr: 25µA @ 1V; Voltage - Forward (Vf) (Max) @ If: 900mV @ 10mA
D13 D15 D17 D20 = CMP-0549-00004-1: Schottky Barrier Rectifier, 40 V Maximum DC Blocking Voltage, -65 to 125 degC, 2-Pin SMA Case, RoHS; Manufacturer: Vishay Semiconductor; IFSM: 40 A; IF(AV): 1 A Max.; VRRM: 40 V Max.; VRMS: 28 V Max.
D18 = CMP-1063-00171-1: as D5 on sheet 4-PPS
R34 R37 R46 R59 = Res1: as R14 on sheet 4-PPS
R35 R36 R38 R39 R60 R61 = Res1: Resistor; Manufacturer: Yageo; Manufacturer Part Number: RC0603JR-075K1L; Resistance (Ohms): 5.1k; Tolerance: ±5%; Power (Watts): 0.1W, 1/10W; Temperature Coefficient: ±100ppm/°C
R40-R42 = Res1: as R5 on sheet 2-Power
R43 = Res1: Resistor; Manufacturer: Yageo; Manufacturer Part Number: RT0603BRD0739KL; Power (Watts): 0.1W, 1/10W; Temperature Coefficient: ±25ppm/°C
R44 = Res1: Resistor; Manufacturer: Yageo; Manufacturer Part Number: AT0603BRD072KL; Power (Watts): 0.1W, 1/10W; Temperature Coefficient: ±25ppm/°C
R45 = Res1: as R15 on sheet 4-PPS

## Sheet 10-DashLEDs.SchDoc
size A4
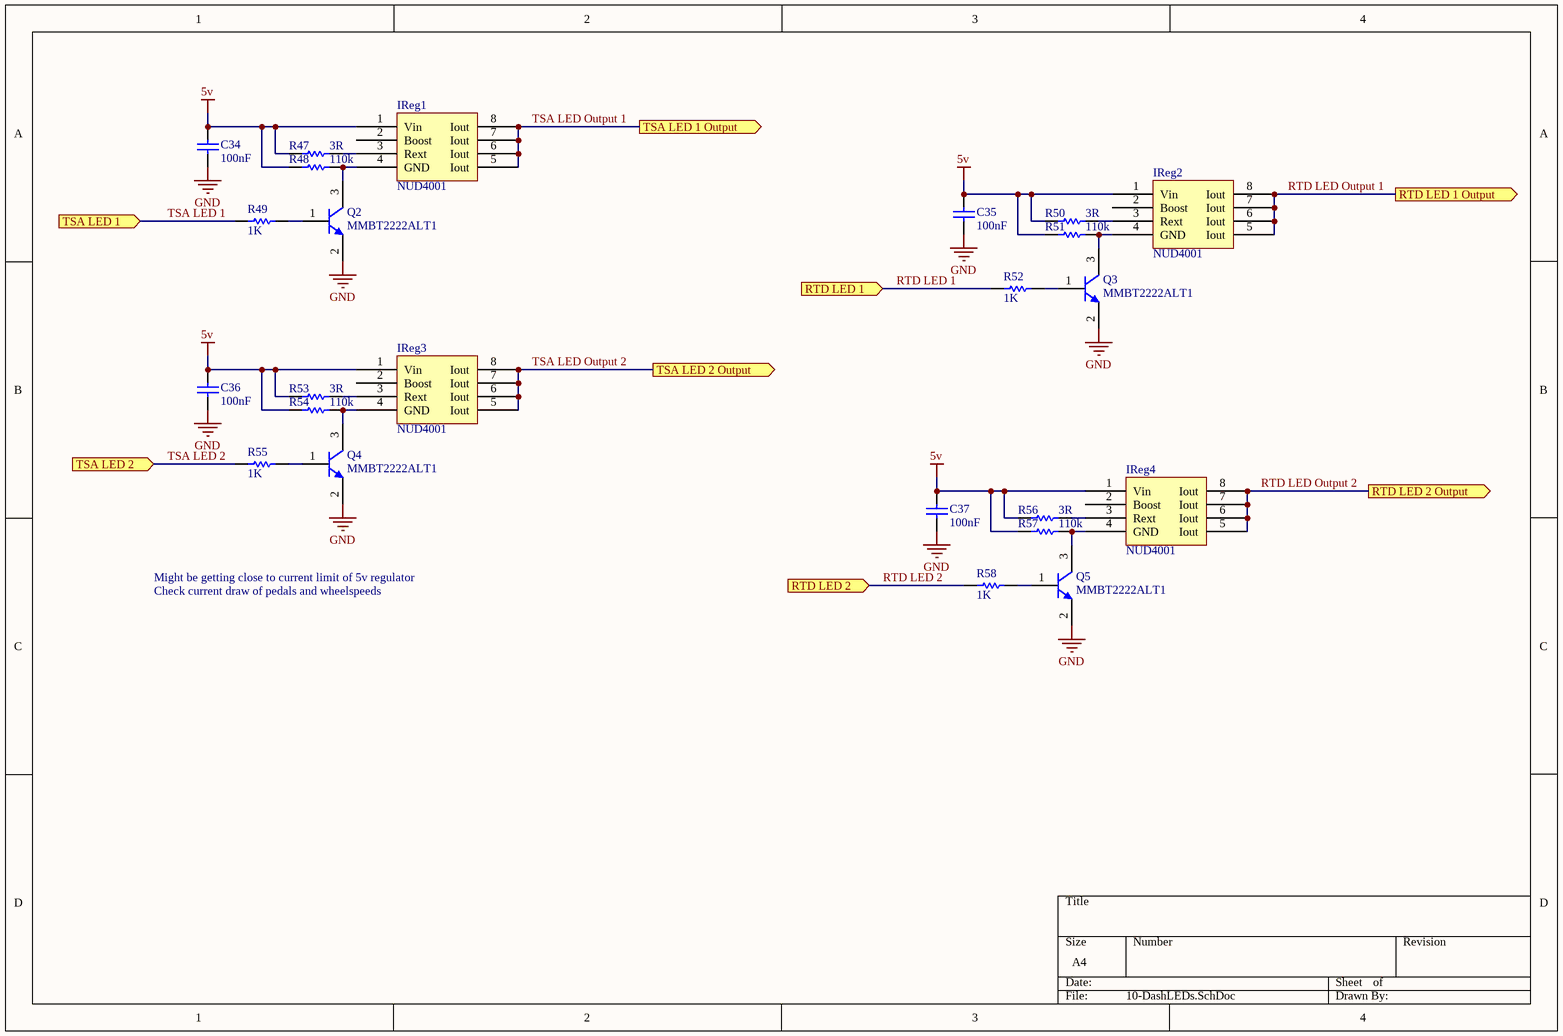
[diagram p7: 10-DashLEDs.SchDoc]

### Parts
C34  value 100nF  [1608[0603]]  (hidden comment: Cap)
C35  value 100nF  [1608[0603]]  (hidden comment: Cap)
C36  value 100nF  [1608[0603]]  (hidden comment: Cap)
C37  value 100nF  [1608[0603]]  (hidden comment: Cap)
IReg1  NUD4001  [SO8_M]
IReg2  NUD4001  [SO8_M]
IReg3  NUD4001  [SO8_M]
IReg4  NUD4001  [SO8_M]
Q2  MMBT2222ALT1  [ONSC-SOT-23-3-318-08_V]
Q3  MMBT2222ALT1  [ONSC-SOT-23-3-318-08_V]
Q4  MMBT2222ALT1  [ONSC-SOT-23-3-318-08_V]
Q5  MMBT2222ALT1  [ONSC-SOT-23-3-318-08_V]
R47  value 3R  [1608[0603]]  (hidden comment: Res1)
R48  value 110k  [1608[0603]]  (hidden comment: Res1)
R49  value 1K  [1608[0603]]  (hidden comment: Res1)
R50  value 3R  [1608[0603]]  (hidden comment: Res1)
R51  value 110k  [1608[0603]]  (hidden comment: Res1)
R52  value 1K  [1608[0603]]  (hidden comment: Res1)
R53  value 3R  [1608[0603]]  (hidden comment: Res1)
R54  value 110k  [1608[0603]]  (hidden comment: Res1)
R55  value 1K  [1608[0603]]  (hidden comment: Res1)
R56  value 3R  [1608[0603]]  (hidden comment: Res1)
R57  value 110k  [1608[0603]]  (hidden comment: Res1)
R58  value 1K  [1608[0603]]  (hidden comment: Res1)

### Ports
RTD LED 1 (in), RTD LED 1 Output (out), RTD LED 2 (in), RTD LED 2 Output (out), TSA LED 1 (in), TSA LED 1 Output (out), TSA LED 2 (in), TSA LED 2 Output (out)

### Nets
5v: C34.2 C35.2 C36.2 C37.2 IReg1.1(Vin) IReg2.1(Vin) IReg3.1(Vin) IReg4.1(Vin) R47.1 R48.1 R50.1 R51.1 R53.1 R54.1 R56.1 R57.1
GND: C34.1 C35.1 C36.1 C37.1 Q2.2(E) Q3.2(E) Q4.2(E) Q5.2(E)
RTD LED 1: R52.2 ; port RTD LED 1
RTD LED 2: R58.2 ; port RTD LED 2
RTD LED Output 1: IReg2.5(Iout) IReg2.6(Iout) IReg2.7(Iout) IReg2.8(Iout) ; port RTD LED 1 Output
RTD LED Output 2: IReg4.5(Iout) IReg4.6(Iout) IReg4.7(Iout) IReg4.8(Iout) ; port RTD LED 2 Output
TSA LED 1: R49.2 ; port TSA LED 1
TSA LED 2: R55.2 ; port TSA LED 2
TSA LED Output 1: IReg1.5(Iout) IReg1.6(Iout) IReg1.7(Iout) IReg1.8(Iout) ; port TSA LED 1 Output
TSA LED Output 2: IReg3.5(Iout) IReg3.6(Iout) IReg3.7(Iout) IReg3.8(Iout) ; port TSA LED 2 Output
NetIReg1_3: IReg1.3(Rext) R47.2
NetIReg1_4: IReg1.4(GND) Q2.3(C) R48.2
NetIReg2_3: IReg2.3(Rext) R50.2
NetIReg2_4: IReg2.4(GND) Q3.3(C) R51.2
NetIReg3_3: IReg3.3(Rext) R53.2
NetIReg3_4: IReg3.4(GND) Q4.3(C) R54.2
NetIReg4_3: IReg4.3(Rext) R56.2
NetIReg4_4: IReg4.4(GND) Q5.3(C) R57.2
NetQ2_1: Q2.1(B) R49.1
NetQ3_1: Q3.1(B) R52.1
NetQ4_1: Q4.1(B) R55.1
NetQ5_1: Q5.1(B) R58.1

Not connected (* = marked no-connect by the designer): IReg1 2(Boost); IReg2 2(Boost); IReg3 2(Boost); IReg4 2(Boost)

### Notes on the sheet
- Might be getting close to current limit of 5v regulator
- Check current draw of pedals and wheelspeeds

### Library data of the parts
C34-C37 = Cap: as C15 on sheet 2-Power
IReg1-IReg4 = LED Currnet Driver, 500mA, 30V max: Manufacturer: ON Semiconductor; Manufacturer Part Number: NUD4001DR2G; Internal Switch(s): Yes; Number of Outputs: 1; Voltage - Supply (Min): 3.6V; Voltage - Supply (Max): 30V; Voltage - Output: 28V; Current - Output / Channel: 500mA; Dimming: PWM
Q2-Q5 = CMP-1048-00593-1: General Purpose Transistor, NPN Silicon, 3-Pin SOT-23, Tape and Reel; Manufacturer: On Semiconductor; fT Min (MHz): 300; IC Continuous (A): 0.6
R47 R50 R53 R56 = Res1: Resistor; Manufacturer: Yageo; Manufacturer Part Number: RC0603FR-072RL; Resistance (Ohms): 2; Tolerance: ±1%; Power (Watts): 0.1W, 1/10W; Temperature Coefficient: ±200ppm/°C
R48 R51 R54 R57 = Res1: Resistor; Manufacturer: Yageo; Manufacturer Part Number: RC0603JR-07110KL; Tolerance: ±5%; Power (Watts): 0.1W, 1/10W; Temperature Coefficient: ±100ppm/°C
R49 R52 R55 R58 = Res1: as R5 on sheet 2-Power

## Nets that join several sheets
3v3: 1-Controller (10 pins), 2-Power (5 pins), 3-CAN (C19.2 C24.2 U2.3 U3.3), 4-PPS (D5.2 D6.2 D7.2 D8.2), 5-Connector (D9.2 D10.2 D11.2), 8-Bluetooth (BT1.2 BT1.16 C28.2 C29.2), 9-Other_Inputs (D18.2)
3v3Ref: 1-Controller (C3.2 U1.13), 2-Power (C11.2 Ref1.6)
5v: 2-Power (C14.2 R6.1 REG1.3), 5-Connector (F1.1 F2.1 F3.1 F4.1), 10-DashLEDs (16 pins)
GND: 1-Controller (19 pins), 2-Power (17 pins), 3-CAN (6 pins), 4-PPS (16 pins), 5-Connector (12 pins), 8-Bluetooth (8 pins), 9-Other_Inputs (17 pins), 10-DashLEDs (8 pins)
Vbatt: 2-Power (10 pins), 9-Other_Inputs (5 pins)
APPS 1 5V: 4-PPS (R16.1 R18.2), 5-Connector (CN1.1)
APPS 2 5V: 4-PPS (R12.1 R14.2), 5-Connector (CN1.7)
Battery In: 2-Power (Q1.3), 5-Connector (CN1.22)
BPPS 1 5V: 4-PPS (R24.1 R26.2), 5-Connector (CN1.4)
BPPS 2 5V: 4-PPS (R20.1 R22.2), 5-Connector (CN1.10)
BT NCTS: 1-Controller (U1.50), 8-Bluetooth (BT1.10)
BT NRTS: 1-Controller (U1.54), 8-Bluetooth (BT1.5)
BT Reset: 1-Controller (U1.53), 8-Bluetooth (BT1.17)
CAN Rx: 1-Controller (U1.62), 3-CAN (R9.2)
CAN Tx: 1-Controller (U1.61), 3-CAN (R10.2)
CAN_N: 3-CAN (D4.2 R11.1 U2.6), 5-Connector (CN1.29)
CAN_P: 3-CAN (D4.1 R11.2 U2.7), 5-Connector (CN1.28)
Dash Toggle: 5-Connector (CN1.26), 9-Other_Inputs (R59.1 R60.1)
NRST: 1-Controller (C1.2 U1.7), 5-Connector (D9.3 F5.1)
RTD BTN: 5-Connector (CN1.14), 9-Other_Inputs (R34.1 R35.1)
RTD LED 1: 1-Controller (U1.35), 10-DashLEDs (R52.2)
RTD LED 2: 1-Controller (U1.33), 10-DashLEDs (R58.2)
RTD LED Output 1: 5-Connector (CN1.17), 10-DashLEDs (IReg2.5 IReg2.6 IReg2.7 IReg2.8)
RTD LED Output 2: 5-Connector (CN1.20), 10-DashLEDs (IReg4.5 IReg4.6 IReg4.7 IReg4.8)
Sensor CAN Rx: 1-Controller (U1.57), 3-CAN (R28.2)
Sensor CAN Tx: 1-Controller (U1.58), 3-CAN (R29.2)
Sensor_CAN_N: 3-CAN (D21.2 R30.1 U3.6), 5-Connector (CN1.32)
Sensor_CAN_P: 3-CAN (D21.1 R30.2 U3.7), 5-Connector (CN1.31)
Shutdown_Tap: 5-Connector (CN1.25), 9-Other_Inputs (R40.2 R42.2)
TSA BTN: 5-Connector (CN1.13), 9-Other_Inputs (R37.1 R38.1)
TSA LED 1: 1-Controller (U1.36), 10-DashLEDs (R49.2)
TSA LED 2: 1-Controller (U1.34), 10-DashLEDs (R55.2)
TSA LED Output 1: 5-Connector (CN1.16), 10-DashLEDs (IReg1.5 IReg1.6 IReg1.7 IReg1.8)
TSA LED Output 2: 5-Connector (CN1.19), 10-DashLEDs (IReg3.5 IReg3.6 IReg3.7 IReg3.8)
UC APPS 1: 1-Controller (U1.8), 4-PPS (C21.2 D6.3 R17.2 R19.2)
UC APPS 2: 1-Controller (U1.21), 4-PPS (C20.2 D5.3 R13.2 R15.2)
UC BPPS 1: 1-Controller (U1.9), 4-PPS (C23.2 D8.3 R25.2 R27.2)
UC BPPS 2: 1-Controller (U1.22), 4-PPS (C22.2 D7.3 R21.2 R23.2)
UC BT Rx: 1-Controller (U1.52), 8-Bluetooth (R32.2)
UC BT Tx: 1-Controller (U1.51), 8-Bluetooth (R33.1)
UC Dash Toggle: 1-Controller (U1.44), 9-Other_Inputs (C38.2 D19.2 R61.2)
UC RTD BTN: 1-Controller (U1.43), 9-Other_Inputs (C30.2 D12.2 R36.2)
UC Shutdown Tap: 1-Controller (U1.26), 9-Other_Inputs (C32.2 D16.2 R41.1)
UC SWCLK: 1-Controller (U1.49), 5-Connector (D11.3 F7.1)
UC SWO: 1-Controller (U1.55), 5-Connector (D10.3 F6.1)
UC TSA BTN: 1-Controller (U1.42), 9-Other_Inputs (C31.2 D14.2 R39.2)
UC Vbatt: 1-Controller (U1.24), 9-Other_Inputs (C33.2 D18.3 R44.2 R45.2)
